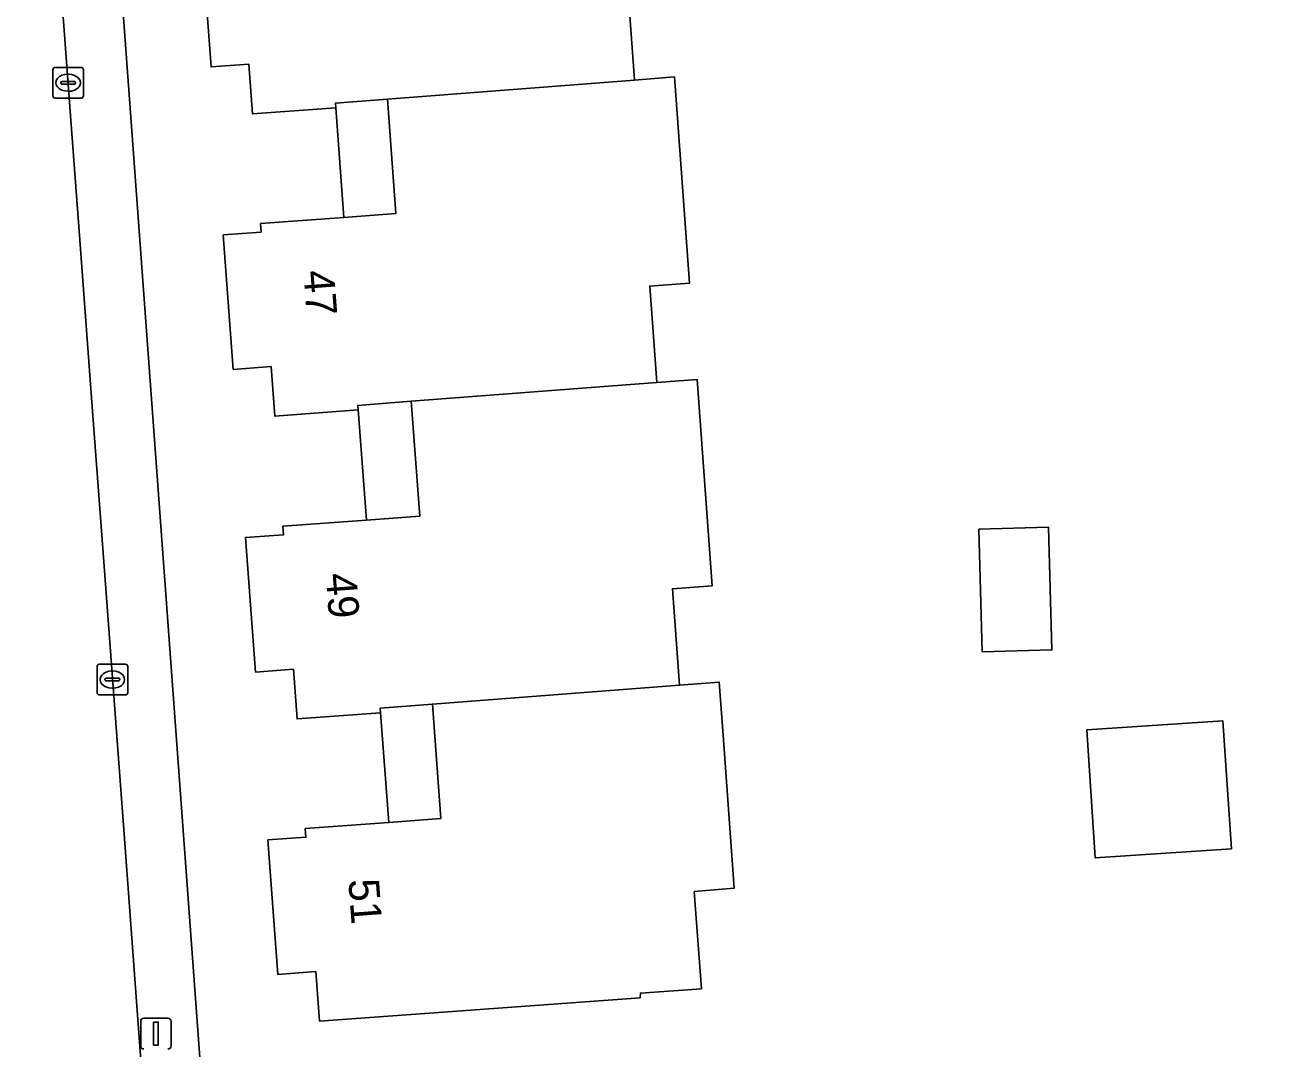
# Model space of a CAD drawing. Extents: x 163426 to 164192, y 380329 to 381641.
# Drawn here: x 163803.06 to 163844.02, y 380942.75 to 380976.16 of the extents above; entities that cross this region are included whole.
import ezdxf

# ---------------------------------------------------------------- set-up
doc = ezdxf.new("R2010")
doc.units = 0
for name, color, linetype in [('IMGEO_Erf', 7, 'Continuous'), ('IMGEO_Kolk', 7, 'Continuous'), ('IMGEO_Lichtmast', 7, 'Continuous'), ('IMGEO_Pand', 7, 'Continuous'), ('IMGEO_Pand_nummerreeks', 7, 'Continuous'), ('IMGEO_Pand_overbouw', 7, 'Continuous'), ('IMGEO_Rijbaan_lokaal_open', 7, 'Continuous'), ('IMGEO_Voetpad_open', 7, 'Continuous')]:
    doc.layers.add(name, color=color, linetype=linetype)

msp = doc.modelspace()

# ---------------------------------------------------------------- linework, layer by layer
at = {"layer": 'IMGEO_Erf'}
for points in [[(163876.92, 381000), (163877.694, 381003.139), (163878.337, 381006.181), (163878.606, 381007.454), (163876.484, 381007.934), (163866.201, 381009.23), (163857.633, 381009.637), (163842.019, 381008.688), (163839.157, 381008.481), (163804.103, 381005.949), (163804.54, 381000), (163809.124, 380937.572)], [(163822.717, 380977.514), (163822.935, 380974.522), (163822.946, 380974.367), (163824.252, 380974.468), (163824.744, 380967.738), (163823.447, 380967.643), (163823.666, 380964.652), (163823.677, 380964.497), (163824.993, 380964.598), (163825.485, 380957.858), (163824.189, 380957.763), (163824.407, 380954.772), (163824.418, 380954.617), (163825.714, 380954.716), (163825.841, 380952.983), (163826.205, 380947.996), (163824.9, 380947.879), (163825.137, 380944.708), (163823.142, 380944.566), (163823.138, 380944.416), (163812.671, 380943.652), (163812.543, 380945.272), (163811.308, 380945.174), (163810.984, 380949.565), (163812.222, 380949.656), (163812.201, 380949.936), (163814.925, 380950.137), (163816.627, 380950.263), (163816.351, 380954), (163814.65, 380953.87), (163814.661, 380953.72), (163811.937, 380953.519), (163811.817, 380955.135), (163810.58, 380955.044), (163810.256, 380959.435), (163811.493, 380959.526), (163811.473, 380959.806), (163814.197, 380960.007), (163815.94, 380960.136), (163815.663, 380963.883), (163813.921, 380963.75), (163813.932, 380963.6), (163811.208, 380963.399), (163811.088, 380965.015), (163809.851, 380964.924), (163809.527, 380969.315), (163810.762, 380969.406), (163810.742, 380969.685), (163813.461, 380969.884), (163815.157, 380970.008), (163814.884, 380973.742), (163813.188, 380973.611), (163813.199, 380973.461), (163810.479, 380973.261), (163810.36, 380974.885), (163809.125, 380974.794), (163808.803, 380979.177)]]:
    msp.add_lwpolyline(points, dxfattribs=at)
for points in [[(163834.186, 380959.712), (163836.46, 380959.777), (163836.576, 380955.769), (163834.301, 380955.704)], [(163837.711, 380953.155), (163842.159, 380953.453), (163842.439, 380949.277), (163837.991, 380948.978)]]:
    msp.add_lwpolyline(points, close=True, dxfattribs=at)
at = {"layer": 'IMGEO_Kolk'}
for p, q in [((163803.962, 380973.854), (163803.962, 380974.706)), ((163804.037, 380974.78), (163804.889, 380974.78)), ((163804.45, 380974.56), (163804.475, 380974.56)), ((163804.963, 380974.706), (163804.963, 380973.854)), ((163804.221, 380974.274), (163804.221, 380974.286)), ((163804.659, 380974.237), (163804.261, 380974.237)), ((163804.264, 380974.323), (163804.662, 380974.323)), ((163804.705, 380974.286), (163804.705, 380974.274)), ((163804.889, 380973.78), (163804.037, 380973.78)), ((163804.473, 380974), (163804.448, 380974)), ((163805.479, 380955.301), (163806.331, 380955.301)), ((163805.404, 380954.375), (163805.404, 380955.227)), ((163805.706, 380954.844), (163806.104, 380954.844)), ((163805.892, 380955.081), (163805.917, 380955.081)), ((163806.405, 380955.227), (163806.405, 380954.375)), ((163805.663, 380954.795), (163805.663, 380954.807)), ((163806.101, 380954.758), (163805.703, 380954.758)), ((163805.915, 380954.521), (163805.89, 380954.521)), ((163806.147, 380954.807), (163806.147, 380954.795)), ((163806.331, 380954.301), (163805.479, 380954.301))]:
    msp.add_line(p, q, dxfattribs=at)
for points in [[(163803.962, 380973.854), (163803.962, 380974.706)], [(163804.037, 380974.78), (163804.889, 380974.78)], [(163804.963, 380974.706), (163804.963, 380973.854)], [(163804.889, 380973.78), (163804.037, 380973.78)], [(163805.479, 380955.301), (163806.331, 380955.301)], [(163805.404, 380954.375), (163805.404, 380955.227)], [(163806.405, 380955.227), (163806.405, 380954.375)], [(163806.331, 380954.301), (163805.479, 380954.301)]]:
    msp.add_lwpolyline(points, dxfattribs=at)
for centre, radius, start, end in [((163804.039, 380974.704), 0.0765, 91.552, 178.448), ((163804.039, 380974.704), 0.0765, 91.552, 178.448), ((163804.887, 380974.704), 0.0765, 1.552, 88.448), ((163804.887, 380974.704), 0.0765, 1.552, 88.448), ((163804.261, 380974.283), 0.0403, 85.8775, 175.7526), ((163804.258, 380974.273), 0.0366, 178.938, 274.7102), ((163804.662, 380974.28), 0.043, 264.8664, 352.4533), ((163804.666, 380974.285), 0.0386, 1.7309, 96.639), ((163804.039, 380973.856), 0.0765, 181.552, 268.448), ((163804.039, 380973.856), 0.0765, 181.552, 268.448), ((163804.887, 380973.856), 0.0765, 271.552, 358.448), ((163804.887, 380973.856), 0.0765, 271.552, 358.448), ((163805.481, 380955.225), 0.0765, 91.552, 178.448), ((163805.481, 380955.225), 0.0765, 91.552, 178.448), ((163806.329, 380955.225), 0.0765, 1.552, 88.448), ((163806.329, 380955.225), 0.0765, 1.552, 88.448), ((163805.703, 380954.804), 0.0403, 85.8775, 175.7526), ((163806.108, 380954.806), 0.0386, 1.7309, 96.639), ((163805.7, 380954.794), 0.0366, 178.938, 274.7102), ((163806.104, 380954.801), 0.043, 264.8664, 352.4533), ((163805.481, 380954.377), 0.0765, 181.552, 268.448), ((163805.481, 380954.377), 0.0765, 181.552, 268.448), ((163806.329, 380954.377), 0.0765, 271.552, 358.448), ((163806.329, 380954.377), 0.0765, 271.552, 358.448)]:
    msp.add_arc(centre, radius, start, end, dxfattribs=at)
for centre, major_axis, ratio, start_param, end_param in [((163804.449, 380974.28), (-0.387, 0.002), 0.722429, 4.712389, 7.853982), ((163804.474, 380974.28), (-0.39, 0.002), 0.717154, 1.570796, 4.712389), ((163805.891, 380954.801), (-0.387, 0.002), 0.722429, 4.712389, 7.853982), ((163805.916, 380954.801), (-0.39, 0.002), 0.717154, 1.570796, 4.712389)]:
    msp.add_ellipse(centre, major_axis=major_axis, ratio=ratio, start_param=start_param, end_param=end_param, dxfattribs=at)
at = {"layer": 'IMGEO_Lichtmast'}
for p, q in [((163806.831, 380942.846), (163806.831, 380943.646)), ((163806.831, 380943.646), (163806.831, 380942.846)), ((163806.931, 380943.746), (163807.721, 380943.746)), ((163807.721, 380943.746), (163806.931, 380943.746)), ((163807.821, 380943.646), (163807.821, 380942.846)), ((163807.821, 380942.846), (163807.821, 380943.646))]:
    msp.add_line(p, q, dxfattribs=at)
msp.add_lwpolyline([(163807.251, 380943.621), (163807.401, 380943.621), (163807.401, 380942.871), (163807.251, 380942.871), (163807.251, 380943.621)], dxfattribs=at)
for centre, start, end in [((163806.931, 380943.646), 90, 180), ((163806.931, 380943.646), 90, 180), ((163807.721, 380943.646), 0, 90), ((163807.721, 380943.646), 360, 90), ((163806.931, 380942.846), 180, 270), ((163806.931, 380942.846), 180, 270), ((163807.721, 380942.846), 270, 0), ((163807.721, 380942.846), 270, 0)]:
    msp.add_arc(centre, 0.1, start, end, dxfattribs=at)
at = {"layer": 'IMGEO_Pand'}
for points in [[(163822.717, 380977.514), (163824.023, 380977.609), (163823.515, 380984.35), (163822.221, 380984.25), (163814.21, 380983.628), (163814.486, 380979.875), (163812.767, 380979.749), (163810.018, 380979.547), (163810.038, 380979.268), (163808.803, 380979.177), (163809.125, 380974.794), (163810.36, 380974.885), (163810.479, 380973.261), (163813.199, 380973.461), (163813.188, 380973.611), (163814.884, 380973.742), (163822.946, 380974.367), (163822.935, 380974.522)], [(163823.447, 380967.643), (163824.744, 380967.738), (163824.252, 380974.468), (163822.946, 380974.367), (163814.884, 380973.742), (163815.157, 380970.008), (163813.461, 380969.884), (163810.742, 380969.685), (163810.762, 380969.406), (163809.527, 380969.315), (163809.851, 380964.924), (163811.088, 380965.015), (163811.208, 380963.399), (163813.932, 380963.6), (163813.921, 380963.75), (163815.663, 380963.883), (163823.677, 380964.497), (163823.666, 380964.652)], [(163825.485, 380957.858), (163824.993, 380964.598), (163823.677, 380964.497), (163815.663, 380963.883), (163815.94, 380960.136), (163814.197, 380960.007), (163811.473, 380959.806), (163811.493, 380959.526), (163810.256, 380959.435), (163810.58, 380955.044), (163811.817, 380955.135), (163811.937, 380953.519), (163814.661, 380953.72), (163814.65, 380953.87), (163816.351, 380954), (163824.418, 380954.617), (163824.407, 380954.772), (163824.189, 380957.763)], [(163834.186, 380959.712), (163834.301, 380955.704), (163836.576, 380955.769), (163836.46, 380959.777)], [(163825.841, 380952.983), (163825.714, 380954.716), (163824.418, 380954.617), (163816.351, 380954), (163816.627, 380950.263), (163814.925, 380950.137), (163812.201, 380949.936), (163812.222, 380949.656), (163810.984, 380949.565), (163811.308, 380945.174), (163812.543, 380945.272), (163812.671, 380943.652), (163823.138, 380944.416), (163823.142, 380944.566), (163825.137, 380944.708), (163824.9, 380947.879), (163826.205, 380947.996)], [(163837.711, 380953.155), (163837.991, 380948.978), (163842.439, 380949.277), (163842.159, 380953.453)]]:
    msp.add_lwpolyline(points, close=True, dxfattribs=at)
at = {"layer": 'IMGEO_Pand_overbouw'}
for points in [[(163814.884, 380973.742), (163813.188, 380973.611), (163813.199, 380973.461), (163813.461, 380969.884), (163815.157, 380970.008)], [(163815.663, 380963.883), (163813.921, 380963.75), (163813.932, 380963.6), (163814.197, 380960.007), (163815.94, 380960.136)], [(163816.351, 380954), (163814.65, 380953.87), (163814.661, 380953.72), (163814.925, 380950.137), (163816.627, 380950.263)]]:
    msp.add_lwpolyline(points, close=True, dxfattribs=at)
at = {"layer": 'IMGEO_Rijbaan_lokaal_open'}
for points in [[(163806.286, 380949.759), (163806.004, 380953.542), (163805.56, 380959.516), (163805.281, 380963.269), (163804.833, 380969.29), (163804.553, 380973.056), (163804.084, 380979.363), (163803.807, 380983.091), (163803.372, 380988.939), (163803.093, 380992.689), (163803.056, 380993.188)], [(163807.509, 380933.308), (163807.416, 380934.56), (163806.286, 380949.759)]]:
    msp.add_lwpolyline(points, dxfattribs=at)
at = {"layer": 'IMGEO_Voetpad_open'}
for points in [[(163809.124, 380937.572), (163804.54, 381000)], [(163803.056, 380993.188), (163803.093, 380992.689), (163803.372, 380988.939), (163803.807, 380983.091), (163804.084, 380979.363), (163804.553, 380973.056), (163804.833, 380969.29), (163805.281, 380963.269), (163805.56, 380959.516), (163806.004, 380953.542), (163806.286, 380949.759), (163807.416, 380934.56), (163811.912, 380935.103)]]:
    msp.add_lwpolyline(points, dxfattribs=at)

# ---------------------------------------------------------------- texts
at = {"layer": 'IMGEO_Pand_nummerreeks'}
for s, p in [('47', (163812.141, 380968.129)), ('49', (163812.87, 380958.249)), ('51', (163813.607, 380948.266))]:
    msp.add_text(s, height=1, rotation=274.2225, dxfattribs=at).set_placement(p)

doc.saveas('drawing.dxf')
